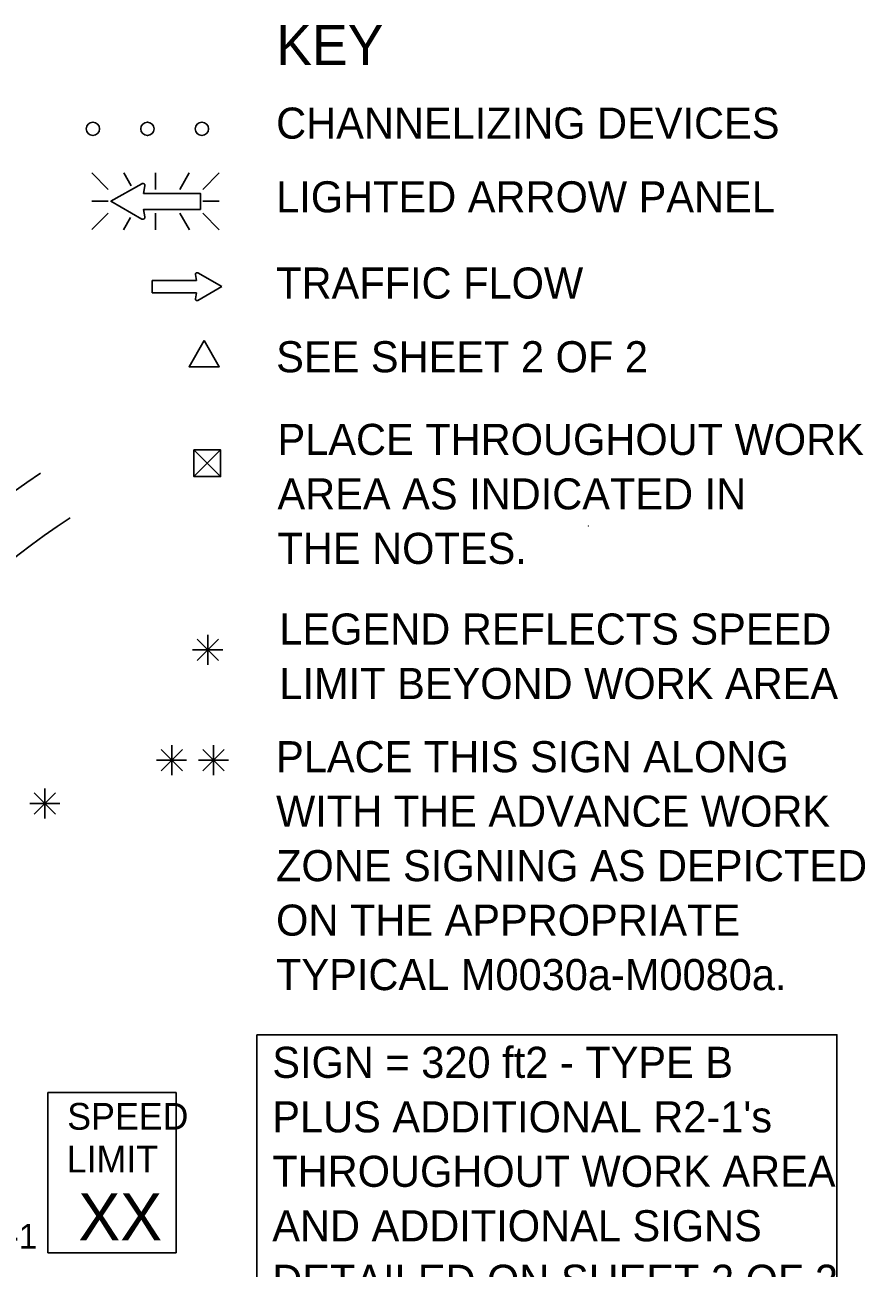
# Model space of a CAD drawing. Extents: x 16556 to 18479, y 5704 to 6974.
# Drawn here: x 17177.7 to 17429.2, y 6550.3 to 6922.2 of the extents above; entities that cross this region are included whole.
import ezdxf

# ---------------------------------------------------------------- set-up
doc = ezdxf.new("R2010")
doc.units = 0
for name, color, linetype in [('MT_SCRATCH_LEVEL_E', 7, 'Continuous'), ('PAVT_EDGE_EX', 7, 'Continuous'), ('TRAFFIC_SIGNS_PR', 7, 'Continuous'), ('TYPICAL_TEXT_DIMEN_EX', 7, 'Continuous'), ('TYPICAL_TEXT_DIMEN_PR', 7, 'Continuous')]:
    doc.layers.add(name, color=color, linetype=linetype)

msp = doc.modelspace()

# ---------------------------------------------------------------- linework, layer by layer
at = {"layer": 'MT_SCRATCH_LEVEL_E'}
for p, q in [((17229.06, 6845.79), (17215.81, 6845.79)), ((17215.81, 6845.79), (17215.81, 6842.05)), ((17228.75, 6847.56), (17229.06, 6845.79)), ((17236.67, 6843.94), (17229.44, 6848.05)), ((17215.81, 6842.05), (17229.06, 6842.05)), ((17229.06, 6842.05), (17228.75, 6840.27)), ((17229.44, 6839.79), (17236.67, 6843.94))]:
    msp.add_line(p, q, dxfattribs=at)
for centre, start, end in [((17229.21, 6847.64), 60.4248, 189.9638), ((17229.21, 6840.2), 170.0362, 299.7731)]:
    msp.add_arc(centre, 0.463, start, end, dxfattribs=at)
at = {"layer": 'PAVT_EDGE_EX'}
for radius in [316, 300]:
    msp.add_arc((17357.65, 6525.15), radius, 123.6935, 180, dxfattribs=at)
at = {"layer": 'TRAFFIC_SIGNS_PR'}
for p, q in [((17197.74, 6877.94), (17202.67, 6873.01)), ((17209.5, 6874.12), (17207.3, 6877.94)), ((17216.82, 6873.01), (17216.82, 6877.94)), ((17224.06, 6873.01), (17226.91, 6877.94)), ((17230.97, 6873.01), (17235.91, 6877.95)), ((17202.67, 6869.45), (17197.74, 6869.45)), ((17230.97, 6869.45), (17235.91, 6869.45)), ((17197.74, 6860.97), (17202.67, 6865.9)), ((17207.25, 6860.96), (17209.37, 6864.63)), ((17216.82, 6865.9), (17216.82, 6860.96)), ((17226.95, 6860.96), (17224.1, 6865.9)), ((17230.97, 6865.9), (17235.91, 6860.96)), ((17184.62, 6602.81), (17223.02, 6602.81)), ((17184.62, 6554.81), (17184.62, 6602.81)), ((17223.02, 6554.81), (17223.02, 6602.81)), ((17184.62, 6554.81), (17223.02, 6554.81))]:
    msp.add_line(p, q, dxfattribs=at)
for points in [[(17212.75, 6874.73), (17203.46, 6869.45), (17212.75, 6864.13)], [(17213.63, 6864.76), (17213.22, 6867.03), (17230.24, 6867.03), (17230.24, 6871.83), (17213.22, 6871.83), (17213.63, 6874.11)]]:
    msp.add_lwpolyline(points, dxfattribs=at)
for centre in [(17198.08, 6891.14), (17214.38, 6891.14), (17230.68, 6891.14)]:
    msp.add_circle(centre, 2, dxfattribs=at)
for centre, radius, start, end in [((17213.04, 6874.21), 0.598, 350.7308, 118.8916), ((17213.04, 6864.66), 0.597, 241.4833, 9.9593)]:
    msp.add_arc(centre, radius, start, end, dxfattribs=at)
at = {"layer": 'TYPICAL_TEXT_DIMEN_EX'}
msp.add_lwpolyline([(17247.1, 6620.06), (17420.75, 6620.06), (17420.75, 6538.3), (17247.1, 6538.3)], close=True, dxfattribs=at)
at = {"layer": 'TYPICAL_TEXT_DIMEN_PR'}
for p, q in [((17228.3, 6795.07), (17236.3, 6787.07)), ((17228.3, 6787.07), (17236.3, 6795.07)), ((17229.24, 6738.49), (17235.62, 6732.11)), ((17235.62, 6738.49), (17229.24, 6732.11)), ((17232.43, 6735.3), (17232.43, 6739.76)), ((17232.43, 6735.3), (17227.9, 6735.3)), ((17232.43, 6735.3), (17235.62, 6735.3)), ((17232.43, 6735.3), (17236.91, 6735.3)), ((17232.43, 6735.3), (17232.43, 6730.8)), ((17218.47, 6705.44), (17224.84, 6699.06)), ((17224.84, 6705.44), (17218.47, 6699.06)), ((17221.65, 6702.25), (17221.65, 6706.71)), ((17231.02, 6705.44), (17237.4, 6699.06)), ((17237.4, 6705.44), (17231.02, 6699.06)), ((17234.21, 6702.25), (17234.21, 6706.71)), ((17221.65, 6702.25), (17217.12, 6702.25)), ((17221.65, 6702.25), (17224.84, 6702.25)), ((17221.65, 6702.25), (17226.13, 6702.25)), ((17221.65, 6702.25), (17221.65, 6697.75)), ((17234.21, 6702.25), (17229.68, 6702.25)), ((17234.21, 6702.25), (17237.4, 6702.25)), ((17234.21, 6702.25), (17238.69, 6702.25)), ((17234.21, 6702.25), (17234.21, 6697.75)), ((17186.9, 6692.45), (17180.52, 6686.07)), ((17180.53, 6692.45), (17186.9, 6686.07)), ((17183.71, 6689.26), (17183.71, 6693.72)), ((17183.71, 6689.26), (17179.18, 6689.26)), ((17183.71, 6689.26), (17186.9, 6689.26)), ((17183.71, 6689.26), (17188.19, 6689.26)), ((17183.71, 6689.26), (17183.71, 6684.76))]:
    msp.add_line(p, q, dxfattribs=at)
for points in [[(17231.39, 6827.76), (17226.86, 6819.93), (17235.91, 6819.93)], [(17228.3, 6795.07), (17228.3, 6787.07), (17236.3, 6787.07), (17236.3, 6795.07)]]:
    msp.add_lwpolyline(points, close=True, dxfattribs=at)
msp.add_open_spline([(17346.31, 6772.35), (17346.33, 6772.35), (17346.33, 6772.35), (17346.33, 6772.35)], degree=2, dxfattribs=at)

# ---------------------------------------------------------------- texts
at = {"layer": 'TRAFFIC_SIGNS_PR'}
for s, height, p in [('PLACE THROUGHOUT WORK', 9.3, (17253.31, 6793.57)), ('AREA AS INDICATED IN', 9.3, (17253.31, 6777.27)), ('THE NOTES.', 9.3, (17253.31, 6760.97)), ('PLACE THIS SIGN ALONG', 9.3, (17252.89, 6698.63)), ('WITH THE ADVANCE WORK', 9.3, (17252.89, 6682.33)), ('ZONE SIGNING AS DEPICTED', 9.3, (17252.89, 6666.03)), ('ON THE APPROPRIATE', 9.3, (17252.89, 6649.73)), ('TYPICAL M0030a-M0080a.', 9.3, (17252.89, 6633.43)), ('SPEED', 8, (17190.39, 6591.67)), ('LIMIT', 8, (17190.23, 6578.87)), ('XX', 14.031, (17193.73, 6558.57)), ('R2-1', 7.44, (17159.87, 6556.06))]:
    msp.add_text(s, height=height, dxfattribs=at).set_placement(p)
at = {"layer": 'TYPICAL_TEXT_DIMEN_EX'}
for s, height, p in [('KEY', 12, (17252.92, 6910.25)), ('CHANNELIZING DEVICES', 9.3, (17252.92, 6888.2)), ('LIGHTED ARROW PANEL', 9.3, (17252.92, 6866.15)), ('TRAFFIC FLOW', 9.3, (17252.92, 6840.35)), ('SEE SHEET 2 OF 2', 9.3, (17252.92, 6818.3)), ('LEGEND REFLECTS SPEED', 9.3, (17253.88, 6736.83)), ('LIMIT BEYOND WORK AREA', 9.3, (17253.88, 6720.53)), ('SIGN = 320 ft2 - TYPE B', 9.3, (17251.76, 6607.18)), ("PLUS ADDITIONAL R2-1's", 9.3, (17251.76, 6590.88)), ('THROUGHOUT WORK AREA', 9.3, (17251.76, 6574.58)), ('AND ADDITIONAL SIGNS', 9.3, (17251.76, 6558.28)), ('DETAILED ON SHEET 2 OF 2', 9.3, (17251.76, 6541.98))]:
    msp.add_text(s, height=height, dxfattribs=at).set_placement(p)

doc.saveas('drawing.dxf')
